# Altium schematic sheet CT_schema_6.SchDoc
size 578 x 363 mm
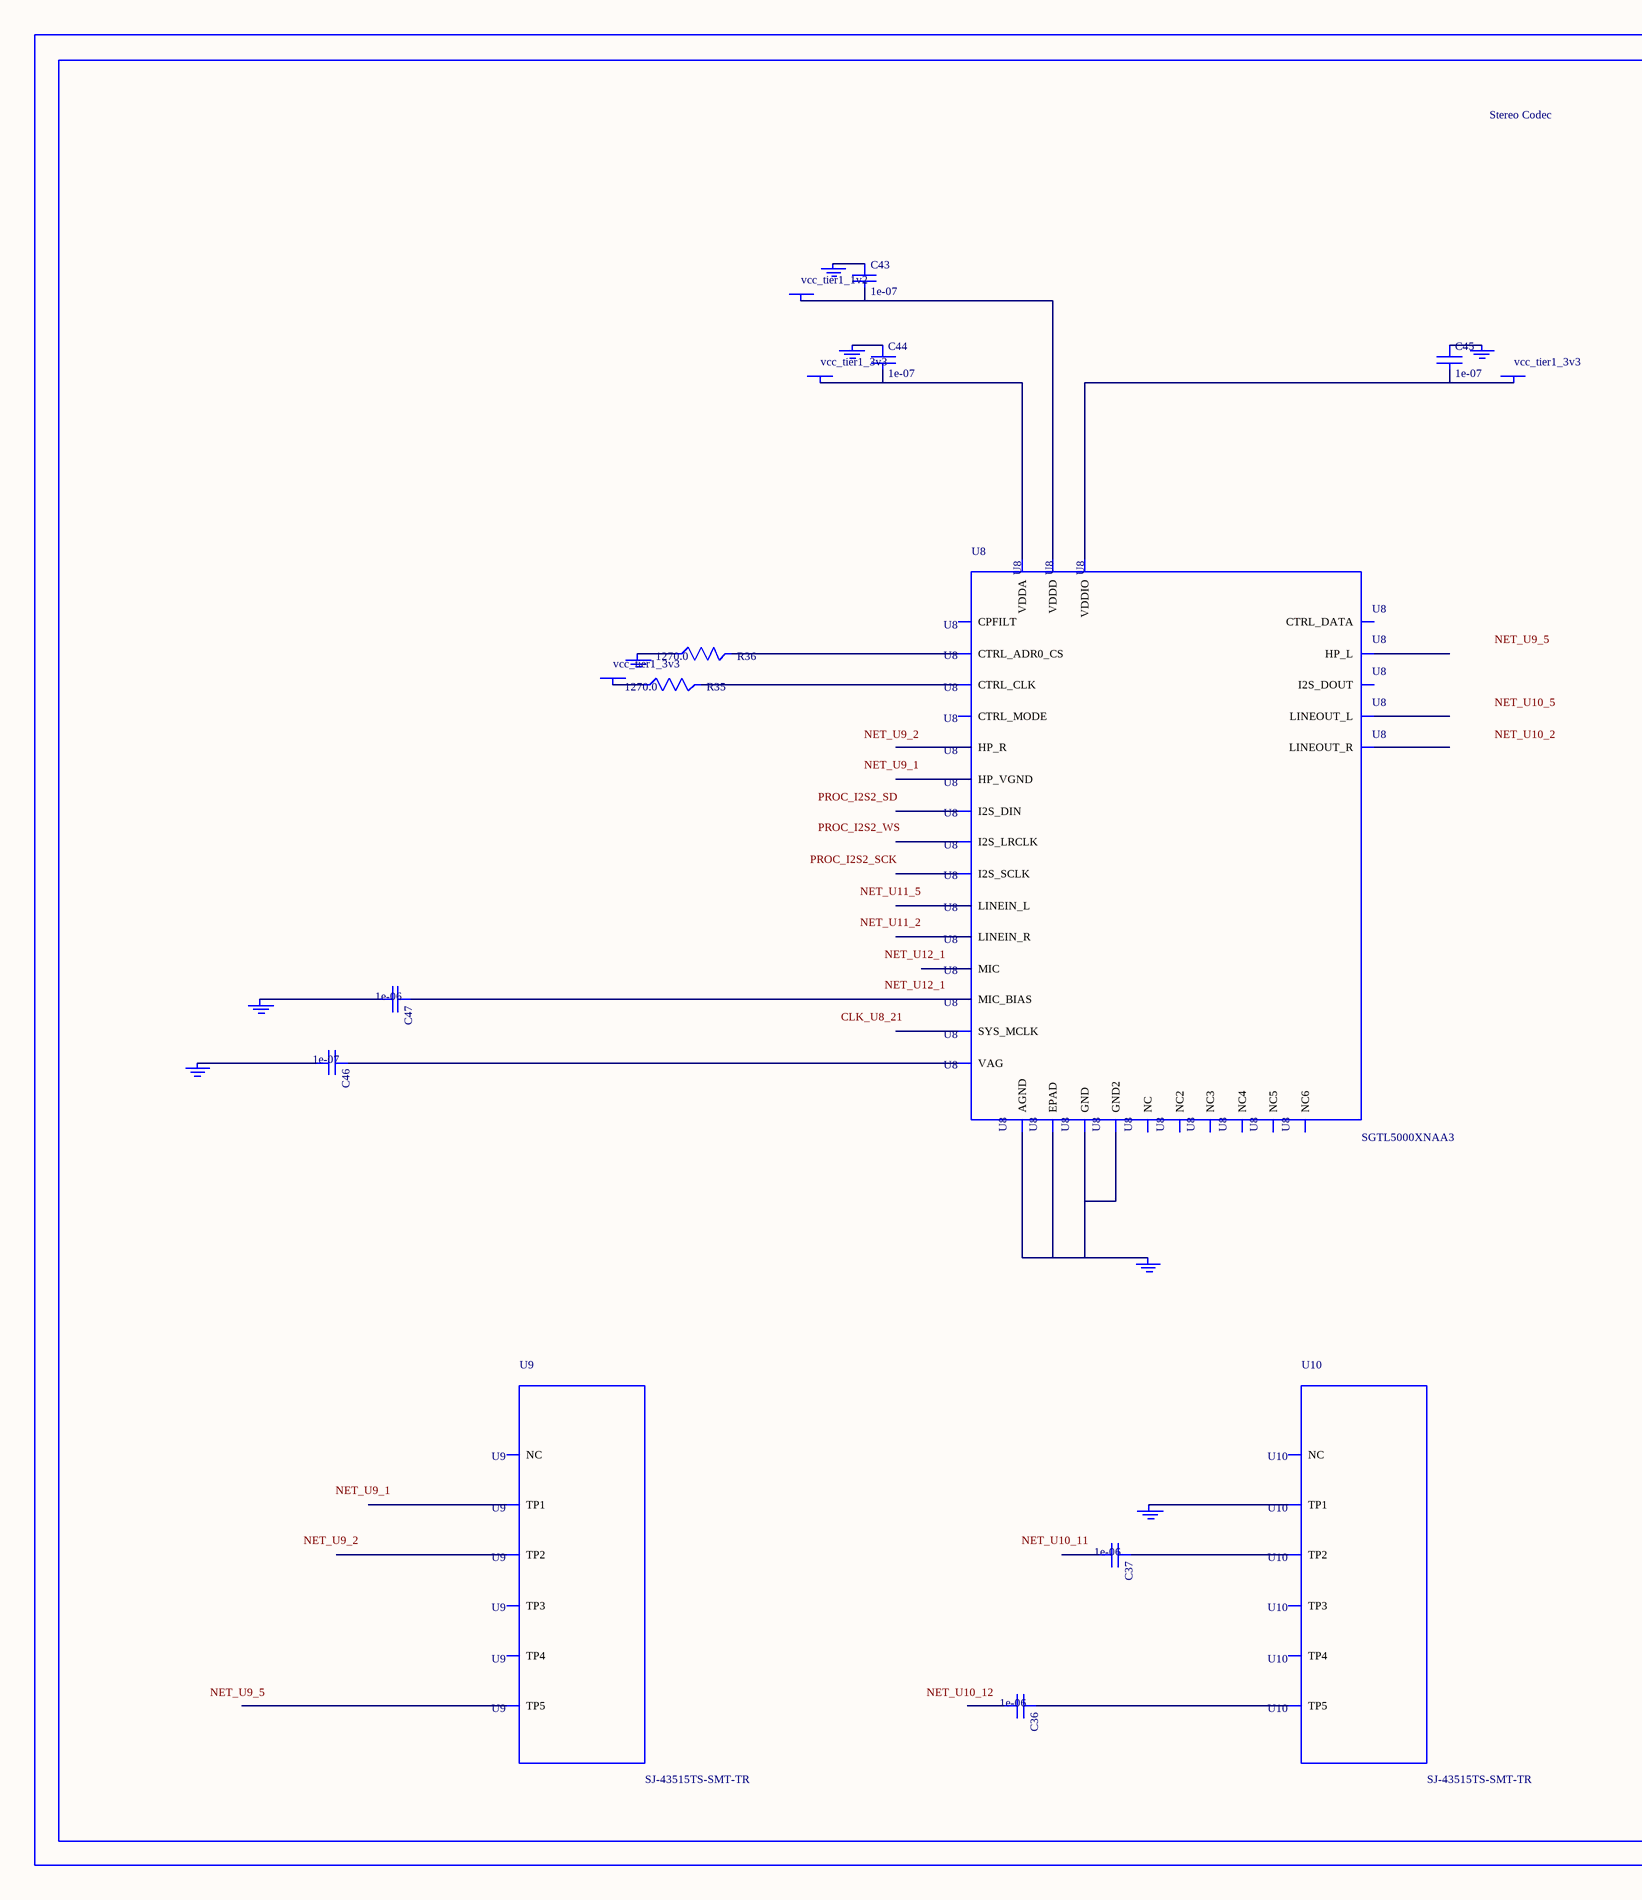
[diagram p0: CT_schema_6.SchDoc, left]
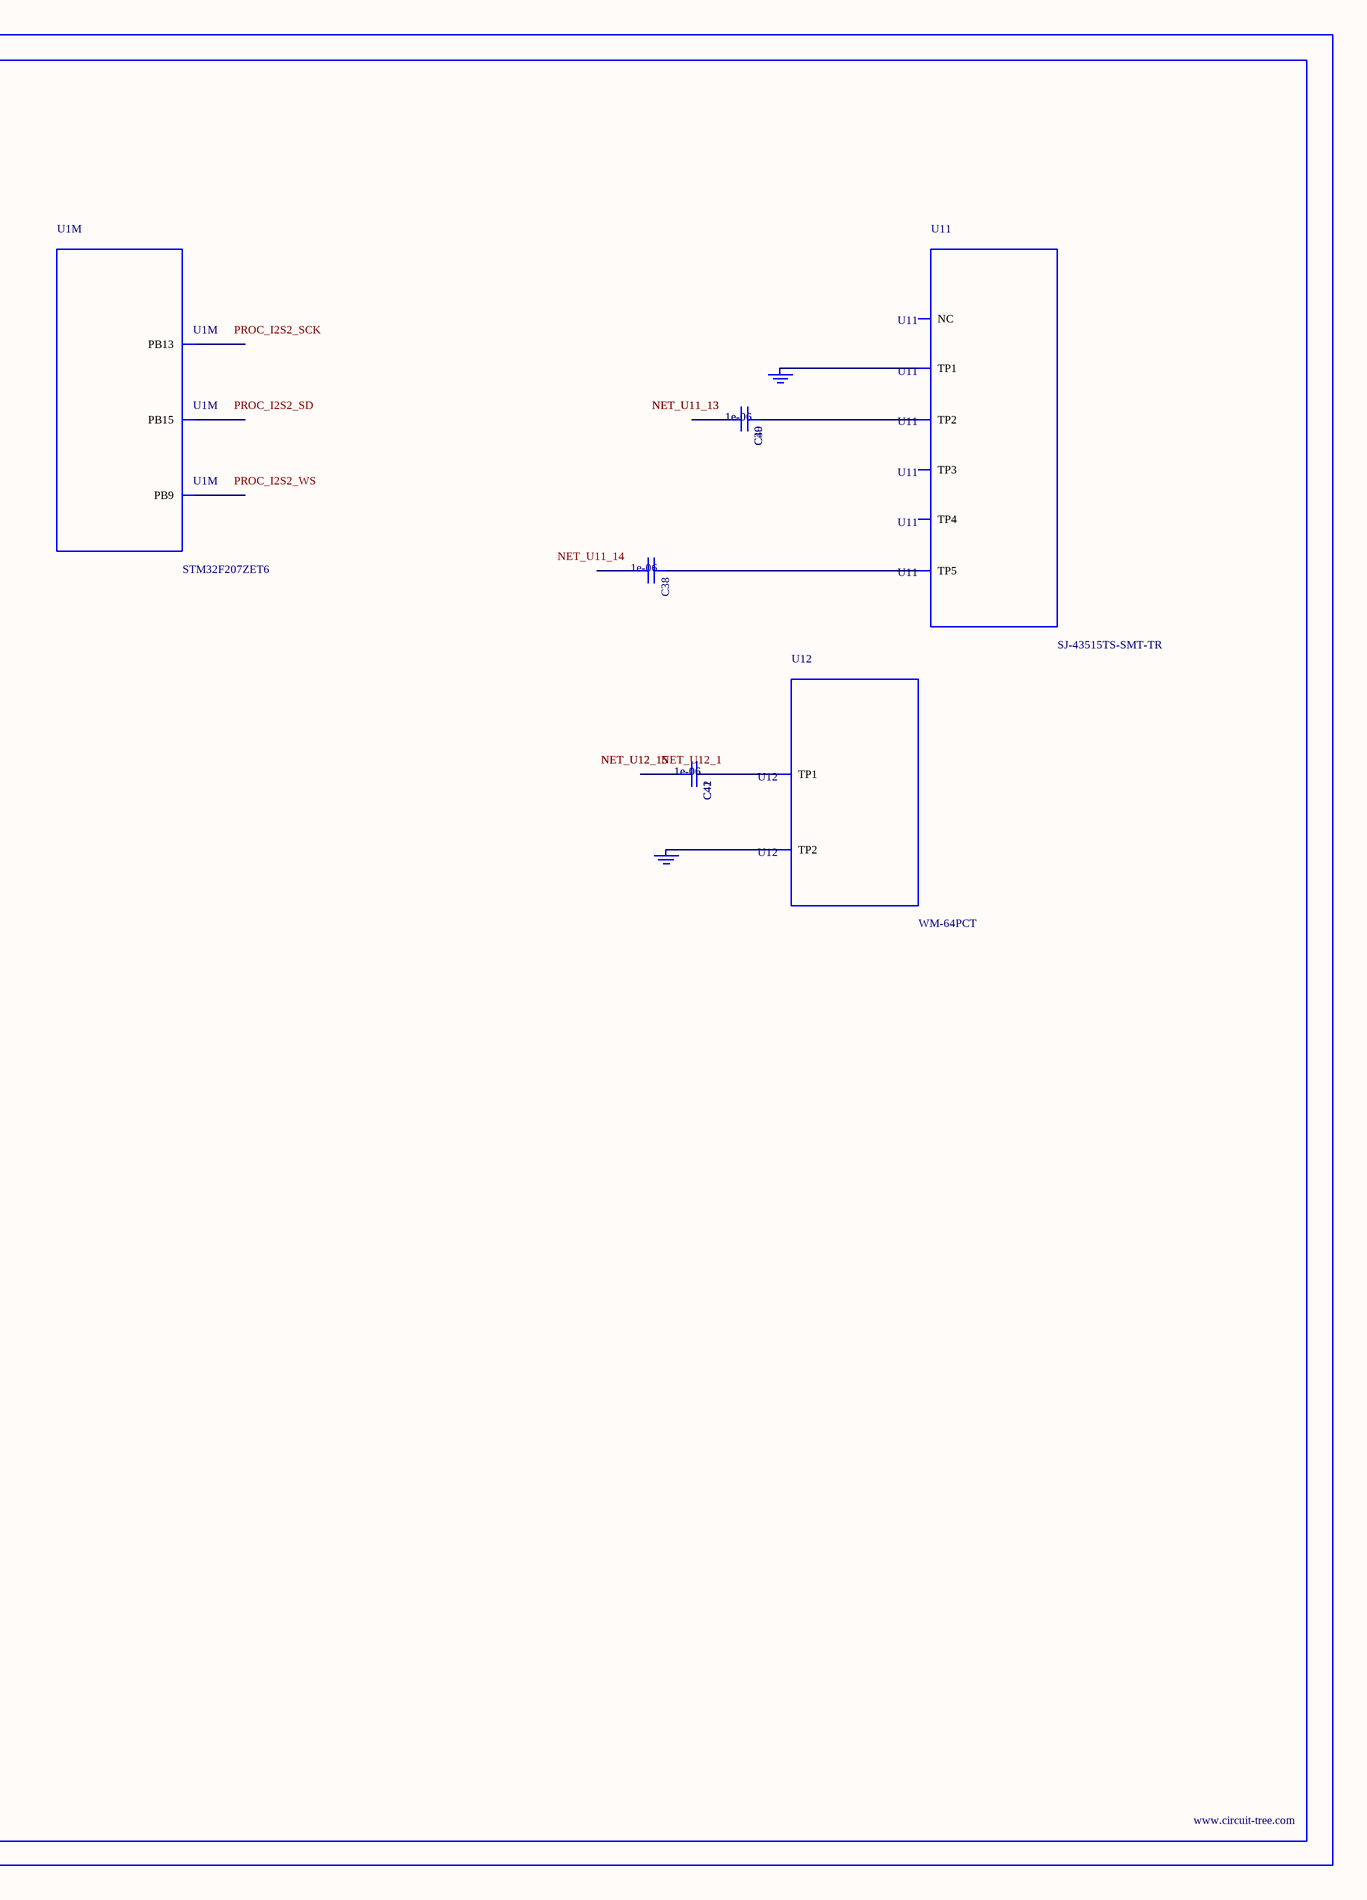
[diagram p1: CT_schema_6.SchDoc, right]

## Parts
BORDER5  (no value)
C36  1e-06  [C0603]
C37  1e-06  [C0603]
C38  1e-06  [C0603]
C39  1e-06  [C0603]
C40  1e-06  [C0603]
C41  1e-06  [C0603]
C42  1e-06  [C0603]
C43  1e-07  [C0402]
C44  1e-07  [C0402]
C45  1e-07  [C0402]
C46  1e-07  [C0402]
C47  1e-06  [C0603]
GND_INSTANCE_5_0  (no value)
GND_INSTANCE_5_1  (no value)
GND_INSTANCE_5_2  (no value)
GND_INSTANCE_5_3  (no value)
GND_INSTANCE_5_4  (no value)
GND_INSTANCE_5_5  (no value)
GND_INSTANCE_5_6  (no value)
GND_INSTANCE_5_7  (no value)
GND_INSTANCE_5_8  (no value)
GND_INSTANCE_5_9  (no value)
GND_INSTANCE_5_10  (no value)
POWER_INSTANCE_5_0  vcc_tier1_3v3
POWER_INSTANCE_5_1  vcc_tier1_3v3
POWER_INSTANCE_5_2  vcc_tier1_3v3
POWER_INSTANCE_5_3  vcc_tier1_1v2
R35  1270.0  [R0603]
R36  1270.0  [R0603]
U1  STM32F207ZET6  [LQFP144]  (part M of 13)
U8  SGTL5000XNAA3  [QFN-32]
U9  SJ-43515TS-SMT-TR  [SJ-43515TS-SMT-TR]
U10  SJ-43515TS-SMT-TR  [SJ-43515TS-SMT-TR]
U11  SJ-43515TS-SMT-TR  [SJ-43515TS-SMT-TR]
U12  WM-64PCT  [WM-64PC]

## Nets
NetC36_1: C36.1 U10.5(TP5)
NetC37_1: C37.1 U10.2(TP2)
NetC38_1: C38.1 U11.5(TP5)
NetC39_1: C39.1 C40.1 U11.2(TP2)
NetC39_2: C39.2 C40.2
NetC41_1: C41.1 C42.1 U12.1(TP1)
NetC41_2: C41.2 C42.2
NetC43_1: C43.1 GND_INSTANCE_5_5.0(GND)
NetC43_2: C43.2 POWER_INSTANCE_5_3.0(PWR) U8.30(VDDD)
NetC44_1: C44.1 GND_INSTANCE_5_1.0(GND)
NetC44_2: C44.2 POWER_INSTANCE_5_0.0(PWR) U8.5(VDDA)
NetC45_1: C45.1 GND_INSTANCE_5_4.0(GND)
NetC45_2: C45.2 POWER_INSTANCE_5_1.0(PWR) U8.20(VDDIO)
NetC46_1: C46.1 U8.10(VAG)
NetC46_2: C46.2 GND_INSTANCE_5_2.0(GND)
NetC47_1: C47.1 U8.16(MIC_BIAS)
NetC47_2: C47.2 GND_INSTANCE_5_3.0(GND)
NetGND_INSTANCE_5_0_0: GND_INSTANCE_5_0.0(GND) U8.1(GND) U8.3(GND2) U8.7(AGND) U8.EXP(EPAD)
NetGND_INSTANCE_5_6_0: GND_INSTANCE_5_6.0(GND) R36.1
NetGND_INSTANCE_5_7_0: GND_INSTANCE_5_7.0(GND) U10.1(TP1)
NetGND_INSTANCE_5_8_0: GND_INSTANCE_5_8.0(GND) GND_INSTANCE_5_9.0(GND) U11.1(TP1)
NetGND_INSTANCE_5_10_0: GND_INSTANCE_5_10.0(GND) U12.2(TP2)
NetPOWER_INSTANCE_5_2_0: POWER_INSTANCE_5_2.0(PWR) R35.1
NetR35_2: R35.2 U8.29(CTRL_CLK)
NetR36_2: R36.2 U8.31(CTRL_ADR0_CS)

Not connected (* = marked no-connect by the designer): C36 2; C37 2; C38 2; U1 74(PB13) 76(PB15) 140(PB9); U8 2(HP_R) 4(HP_VGND) 6(HP_L) 8(NC) 9(NC2) 11(LINEOUT_R) 12(LINEOUT_L) 13(LINEIN_R) 14(LINEIN_L) 15(MIC) 17(NC3) 18(CPFILT) 19(NC4) 21(SYS_MCLK) 22(NC5) 23(I2S_LRCLK) 24(I2S_SCLK) 25(I2S_DOUT) 26(I2S_DIN) 27(CTRL_DATA) 28(NC6) 32(CTRL_MODE); U9 1(TP1) 2(TP2) 3(TP3) 4(TP4) 5(TP5) 6(NC); U10 3(TP3) 4(TP4) 6(NC); U11 3(TP3) 4(TP4) 6(NC)

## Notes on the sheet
- Labels drawn without touching a wire or pin: CLK_U8_21, NET_U9_1, NET_U9_2, NET_U9_5, NET_U10_2, NET_U10_5, NET_U10_11, NET_U10_12, NET_U11_2, NET_U11_5, NET_U11_14, NET_U12_1, PROC_I2S2_SCK, PROC_I2S2_SD, PROC_I2S2_WS

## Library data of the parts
BORDER5 = BORDER_PAGE5
C36-C42 C47 = C0603C105K3RACTU
C43-C46 = C0402C104K3RACTU
GND_INSTANCE_5_0-GND_INSTANCE_5_10 = GND
POWER_INSTANCE_5_0-POWER_INSTANCE_5_3 = PWR
R35 R36 = RC0603FR-071K27L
